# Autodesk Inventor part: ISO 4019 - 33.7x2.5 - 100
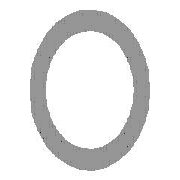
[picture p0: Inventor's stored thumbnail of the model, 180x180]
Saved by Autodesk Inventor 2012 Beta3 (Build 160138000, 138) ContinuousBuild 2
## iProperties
_CCFamilyMember: 8
_CCFamilyDisplayName: ISO 4019 (Circular Hollow Section - Cold Formed) - Sructural steels, Cold-formed, welded, structural hollow sections
_FrameMemberDoc: Frame Member File
_Version: 15.0.0
_GetPNFromCC: 1
Created: 2010-11
Part Number: ISO 4019 - 33.7x2.5 - 100
Material: Steel, Mild
Description: Sructural steels, Cold-formed, welded, structural hollow sections
Document SubType Name: Modeling
Standard: ISO
Designer: Beta-8540w
Standard Revision: Second edition 2001-09-01
Standards Organization: ISO
Language: en-US
Size Designation: 33.7x2.5
Categories: <MemberInstance><Categories><Category DisplayName="Structural Shapes" InternalName="089c4875-fa83-4c05-b084-43b9cc11f5ed" Mnemonic="GRDR"><CategoryParameter Dis
Stock Number: 33.7x2.5
Density: 7.86 g/cm^3
IsCustomPart: 1
G_L: 100.000 mm
G_W: 33.700 mm
G_H: 33.700 mm
Author: Beta-8540w
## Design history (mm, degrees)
node "Start plane"
node "End plane"
sketch "Sketch"
  geometry: C1 r 14.35 at (0, 0); C2 r 16.85 at (0, 0); 2 further points
  constraints: 3 coincident, 2 centre point
  dimensions: "d0" = 33.7 diameter of C2 (= G_H); "d1" = 2.5 radial gap between concentric circles of C2 C1 (= G_T)
extrude "Body" new body sketch "Sketch" stored distance "d2" = 100 (= G_L); taper "d3" = 0 deg
node "Driven Length"
  sketch "Sketch3"
    geometry: L1 (0, 0)-(10, 0) reference
    constraints: 2 end point, 1 horizontal
  workplane "Work Plane3"
  sketch "Sketch4"
    geometry: L1 (-2, 0)-(12, 0) reference; L2 (-2, 100)-(12, 100) reference
    dimensions: "d7" = 100 distance between parallel lines of L1 L2 (derived)
body "Solid1"
other parameters: "G_H" = 33.7 [user parameter; used in 1 equation term], "G_T" = 2.5 [user parameter; used in 1 equation term], "G_L" = 100 (= d7) [user parameter; used in 1 equation term], "G_OFFSET_START" = 0 [user parameter; used in 1 equation term], "G_OFFSET_END" = 0 [user parameter; used in 1 equation term], "d4" = 0 (computed from G_OFFSET_START), "d6" = 90 deg, "MAS" = 0.192 [user parameter]
